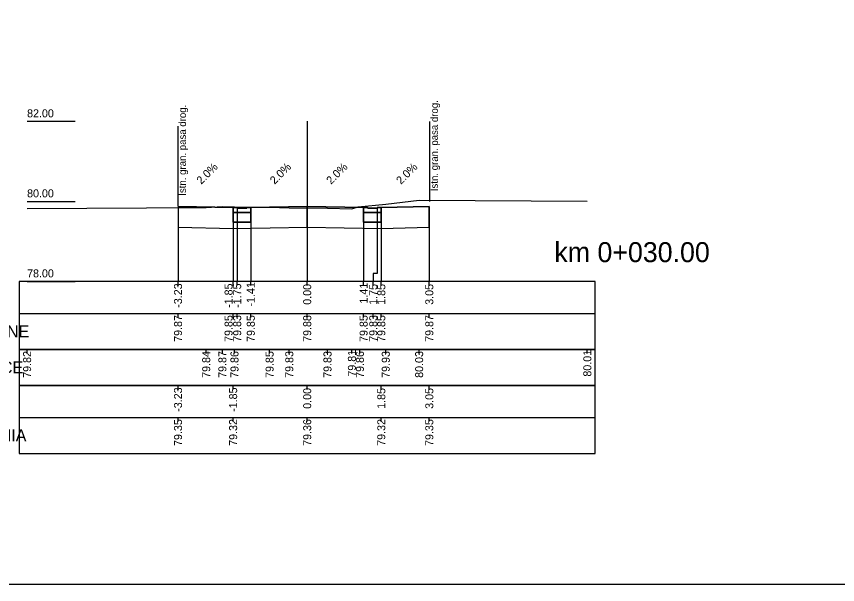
# Model space of a CAD drawing. Extents: x 7492871 to 7493499, y 5802964 to 5802992.
# Drawn here: x 7492882.66 to 7492903.18, y 5802963.88 to 5802978.08 of the extents above; entities that cross this region are included whole.
import ezdxf

# ---------------------------------------------------------------- set-up
doc = ezdxf.new("R2010")
doc.units = 0
for name, color, linetype in [('_wydruk', 7, 'Continuous'), ('opisy_ramki_pop', 7, 'Continuous'), ('pop_comp_kostka', 7, 'Continuous'), ('pop_comp_lawa', 7, 'Continuous'), ('pop_comp_scieralna', 7, 'Continuous'), ('pop_granica_istn', 7, 'Continuous'), ('pop_opis', 7, 'Continuous'), ('pop_os', 7, 'Continuous'), ('pop_pikietaz', 7, 'Continuous'), ('pop_teren', 7, 'Continuous')]:
    doc.layers.add(name, color=color, linetype=linetype)

msp = doc.modelspace()

# ---------------------------------------------------------------- linework, layer by layer
msp.add_lwpolyline([(7492886.697, 5802973.334), (7492888.074, 5802973.306), (7492888.174, 5802973.306), (7492888.175, 5802973.286), (7492888.414, 5802973.286), (7492888.415, 5802973.306), (7492888.515, 5802973.306), (7492889.925, 5802973.334), (7492891.335, 5802973.306), (7492891.435, 5802973.306), (7492891.436, 5802973.286), (7492891.675, 5802973.286), (7492891.676, 5802973.306), (7492891.776, 5802973.306), (7492892.976, 5802973.33)])
at = {"layer": '_wydruk'}
msp.add_lwpolyline([(7492871.369, 5802992.281), (7493499.283, 5802992.281), (7493499.283, 5802963.881), (7492871.369, 5802963.881)], close=True, dxfattribs=at)
at = {"layer": 'opisy_ramki_pop'}
for points in [[(7492886.697, 5802972.814), (7492886.697, 5802971.659), (7492886.697, 5802971.659), (7492886.697, 5802971.459)], [(7492888.074, 5802972.777), (7492888.074, 5802971.659), (7492888.074, 5802971.659), (7492888.074, 5802971.459)], [(7492889.925, 5802972.814), (7492889.925, 5802971.659), (7492889.925, 5802971.659), (7492889.925, 5802971.459)], [(7492891.776, 5802972.777), (7492891.776, 5802971.659), (7492891.776, 5802971.659), (7492891.776, 5802971.459)], [(7492892.976, 5802972.81), (7492892.976, 5802971.659), (7492892.976, 5802971.659), (7492892.976, 5802971.459)]]:
    msp.add_lwpolyline(points, dxfattribs=at)
at = {"layer": 'pop_comp_kostka'}
for p, q in [((7492888.174, 5802973.306), (7492888.074, 5802973.306)), ((7492888.074, 5802973.306), (7492888.074, 5802973.176)), ((7492888.074, 5802973.176), (7492888.515, 5802973.176)), ((7492888.175, 5802973.286), (7492888.174, 5802973.306)), ((7492888.414, 5802973.286), (7492888.175, 5802973.286)), ((7492888.415, 5802973.306), (7492888.414, 5802973.286)), ((7492888.515, 5802973.306), (7492888.415, 5802973.306)), ((7492888.515, 5802973.176), (7492888.515, 5802973.306)), ((7492891.435, 5802973.306), (7492891.335, 5802973.306)), ((7492891.335, 5802973.306), (7492891.335, 5802973.176)), ((7492891.335, 5802973.176), (7492891.776, 5802973.176)), ((7492891.436, 5802973.286), (7492891.435, 5802973.306)), ((7492891.675, 5802973.286), (7492891.436, 5802973.286)), ((7492891.676, 5802973.306), (7492891.675, 5802973.286)), ((7492891.776, 5802973.306), (7492891.676, 5802973.306)), ((7492891.776, 5802973.176), (7492891.776, 5802973.306))]:
    msp.add_line(p, q, dxfattribs=at)
at = {"layer": 'pop_comp_lawa'}
for p, q in [((7492888.515, 5802973.176), (7492888.074, 5802973.176)), ((7492888.074, 5802973.176), (7492888.074, 5802972.936)), ((7492888.515, 5802972.936), (7492888.515, 5802973.176)), ((7492891.776, 5802973.176), (7492891.335, 5802973.176)), ((7492891.335, 5802973.176), (7492891.335, 5802972.936)), ((7492891.776, 5802972.936), (7492891.776, 5802973.176)), ((7492888.074, 5802972.936), (7492888.515, 5802972.936)), ((7492891.335, 5802972.936), (7492891.776, 5802972.936))]:
    msp.add_line(p, q, dxfattribs=at)
at = {"layer": 'pop_comp_scieralna'}
for p, q in [((7492888.074, 5802973.306), (7492886.697, 5802973.334)), ((7492886.697, 5802973.334), (7492886.697, 5802972.814)), ((7492888.074, 5802972.936), (7492888.074, 5802973.306)), ((7492889.925, 5802973.334), (7492888.515, 5802973.306)), ((7492888.515, 5802973.306), (7492888.515, 5802972.936)), ((7492889.925, 5802972.814), (7492889.925, 5802973.334)), ((7492891.335, 5802973.306), (7492889.925, 5802973.334)), ((7492889.925, 5802973.334), (7492889.925, 5802972.814)), ((7492891.335, 5802972.936), (7492891.335, 5802973.306)), ((7492892.976, 5802973.33), (7492891.776, 5802973.306)), ((7492891.776, 5802973.306), (7492891.776, 5802972.936)), ((7492892.976, 5802972.81), (7492892.976, 5802973.33)), ((7492886.697, 5802972.814), (7492888.074, 5802972.777)), ((7492888.515, 5802972.936), (7492888.074, 5802972.936)), ((7492888.074, 5802972.777), (7492889.925, 5802972.814)), ((7492889.925, 5802972.814), (7492891.776, 5802972.777)), ((7492891.776, 5802972.936), (7492891.335, 5802972.936)), ((7492891.776, 5802972.777), (7492892.976, 5802972.81))]:
    msp.add_line(p, q, dxfattribs=at)
at = {"layer": 'pop_granica_istn'}
for p, q in [((7492892.993, 5802973.952), (7492892.993, 5802975.452)), ((7492886.697, 5802973.838), (7492886.697, 5802975.338)), ((7492886.697, 5802973.338), (7492886.697, 5802973.838)), ((7492892.993, 5802973.452), (7492892.993, 5802973.952))]:
    msp.add_line(p, q, dxfattribs=at)
at = {"layer": 'pop_opis'}
for p, q in [((7492882.925, 5802975.459), (7492884.125, 5802975.459)), ((7492882.925, 5802973.459), (7492884.125, 5802973.459)), ((7492882.725, 5802971.459), (7492882.725, 5802969.759)), ((7492882.725, 5802971.459), (7492882.725, 5802969.759)), ((7492882.725, 5802971.459), (7492882.725, 5802969.759)), ((7492882.725, 5802971.459), (7492882.725, 5802969.759)), ((7492882.925, 5802971.459), (7492884.125, 5802971.459)), ((7492886.697, 5802971.359), (7492886.697, 5802971.459)), ((7492888.074, 5802971.359), (7492888.074, 5802971.459)), ((7492888.175, 5802971.359), (7492888.175, 5802971.459)), ((7492888.515, 5802971.359), (7492888.515, 5802971.459)), ((7492889.925, 5802971.359), (7492889.925, 5802971.459)), ((7492891.335, 5802971.359), (7492891.335, 5802971.459)), ((7492891.576, 5802971.359), (7492891.576, 5802971.459)), ((7492891.776, 5802971.359), (7492891.776, 5802971.459)), ((7492892.976, 5802971.359), (7492892.976, 5802971.459)), ((7492882.725, 5802970.659), (7492897.125, 5802970.659)), ((7492882.725, 5802970.659), (7492897.125, 5802970.659)), ((7492882.725, 5802970.659), (7492897.125, 5802970.659)), ((7492882.725, 5802970.659), (7492897.125, 5802970.659)), ((7492886.697, 5802970.559), (7492886.697, 5802970.659)), ((7492888.074, 5802970.559), (7492888.074, 5802970.659)), ((7492888.175, 5802970.559), (7492888.175, 5802970.659)), ((7492888.515, 5802970.559), (7492888.515, 5802970.659)), ((7492889.925, 5802970.559), (7492889.925, 5802970.659)), ((7492891.335, 5802970.559), (7492891.335, 5802970.659)), ((7492891.576, 5802970.559), (7492891.576, 5802970.659)), ((7492891.776, 5802970.559), (7492891.776, 5802970.659)), ((7492892.976, 5802970.559), (7492892.976, 5802970.659)), ((7492882.725, 5802969.759), (7492882.725, 5802968.859)), ((7492882.925, 5802969.659), (7492882.925, 5802969.759)), ((7492887.401, 5802969.659), (7492887.401, 5802969.759)), ((7492887.805, 5802969.659), (7492887.805, 5802969.759)), ((7492888.108, 5802969.659), (7492888.108, 5802969.759)), ((7492888.985, 5802969.659), (7492888.985, 5802969.759)), ((7492889.477, 5802969.659), (7492889.477, 5802969.759)), ((7492890.432, 5802969.659), (7492890.432, 5802969.759)), ((7492891.042, 5802969.659), (7492891.042, 5802969.759)), ((7492891.242, 5802969.659), (7492891.242, 5802969.759)), ((7492891.888, 5802969.659), (7492891.888, 5802969.759)), ((7492892.722, 5802969.659), (7492892.722, 5802969.759)), ((7492896.925, 5802969.659), (7492896.925, 5802969.759)), ((7492882.725, 5802968.859), (7492882.725, 5802967.159)), ((7492886.697, 5802968.759), (7492886.697, 5802968.859)), ((7492888.074, 5802968.759), (7492888.074, 5802968.859)), ((7492889.925, 5802968.759), (7492889.925, 5802968.859)), ((7492891.776, 5802968.759), (7492891.776, 5802968.859)), ((7492892.976, 5802968.759), (7492892.976, 5802968.859)), ((7492882.725, 5802968.059), (7492897.125, 5802968.059)), ((7492886.697, 5802967.959), (7492886.697, 5802968.059)), ((7492888.074, 5802967.959), (7492888.074, 5802968.059)), ((7492889.925, 5802967.959), (7492889.925, 5802968.059)), ((7492891.776, 5802967.959), (7492891.776, 5802968.059)), ((7492892.976, 5802967.959), (7492892.976, 5802968.059))]:
    msp.add_line(p, q, dxfattribs=at)
for points in [[(7492886.697, 5802973.334), (7492886.697, 5802971.659), (7492886.697, 5802971.659), (7492886.697, 5802971.459)], [(7492888.074, 5802973.306), (7492888.074, 5802971.659), (7492888.074, 5802971.659), (7492888.074, 5802971.459)], [(7492888.175, 5802973.286), (7492888.175, 5802971.659), (7492888.175, 5802971.659), (7492888.175, 5802971.459)], [(7492888.515, 5802973.306), (7492888.515, 5802971.659), (7492888.515, 5802971.659), (7492888.515, 5802971.459)], [(7492889.925, 5802973.334), (7492889.925, 5802971.659), (7492889.925, 5802971.659), (7492889.925, 5802971.459)], [(7492891.335, 5802973.306), (7492891.335, 5802971.659), (7492891.335, 5802971.659), (7492891.335, 5802971.459)], [(7492891.675, 5802973.286), (7492891.675, 5802971.659), (7492891.576, 5802971.659), (7492891.576, 5802971.459)], [(7492891.776, 5802973.306), (7492891.776, 5802971.659), (7492891.776, 5802971.659), (7492891.776, 5802971.459)], [(7492892.976, 5802973.33), (7492892.976, 5802971.659), (7492892.976, 5802971.659), (7492892.976, 5802971.459)]]:
    msp.add_lwpolyline(points, dxfattribs=at)
for points in [[(7492882.725, 5802971.459), (7492882.725, 5802969.759), (7492897.125, 5802969.759), (7492897.125, 5802971.459)], [(7492882.725, 5802971.459), (7492882.725, 5802969.759), (7492897.125, 5802969.759), (7492897.125, 5802971.459)], [(7492882.725, 5802971.459), (7492882.725, 5802969.759), (7492897.125, 5802969.759), (7492897.125, 5802971.459)], [(7492882.725, 5802971.459), (7492882.725, 5802969.759), (7492897.125, 5802969.759), (7492897.125, 5802971.459)], [(7492882.725, 5802969.759), (7492882.725, 5802968.859), (7492897.125, 5802968.859), (7492897.125, 5802969.759)], [(7492882.725, 5802968.859), (7492882.725, 5802967.159), (7492897.125, 5802967.159), (7492897.125, 5802968.859)]]:
    msp.add_lwpolyline(points, close=True, dxfattribs=at)
at = {"layer": 'pop_os'}
msp.add_line((7492889.925, 5802975.459), (7492889.925, 5802971.459), dxfattribs=at)
at = {"layer": 'pop_teren'}
msp.add_lwpolyline([(7492882.925, 5802973.281), (7492887.401, 5802973.303), (7492887.805, 5802973.333), (7492888.108, 5802973.323), (7492888.985, 5802973.313), (7492889.477, 5802973.293), (7492890.432, 5802973.285), (7492891.042, 5802973.271), (7492891.195, 5802973.32), (7492891.888, 5802973.385), (7492892.722, 5802973.489), (7492896.925, 5802973.467)], dxfattribs=at)

# ---------------------------------------------------------------- texts
at = {"layer": 'pop_granica_istn'}
for p in [(7492886.895, 5802973.599), (7492893.191, 5802973.713)]:
    msp.add_text('Istn. gran. pasa drog.', height=0.18, rotation=90, dxfattribs=at).set_placement(p)
at = {"layer": 'pop_opis'}
for s, height, p in [('82.00', 0.2, (7492882.925, 5802975.559)), ('80.00', 0.2, (7492882.925, 5802973.559)), ('78.00', 0.2, (7492882.925, 5802971.559)), ('RZĘDNE PROJEKTOWANE', 0.3, (7492877.853, 5802970.059)), ('RZĘDNE PROJEKTOWANE', 0.3, (7492877.853, 5802970.059)), ('RZĘDNE PROJEKTOWANE', 0.3, (7492877.853, 5802970.059)), ('RZĘDNE PROJEKTOWANE', 0.3, (7492877.853, 5802970.059)), ('RZĘDNE ISTNIEJĄCE', 0.3, (7492878.749, 5802969.159)), ('RZĘDNE KORYTOWANIA', 0.3, (7492878.139, 5802967.459))]:
    msp.add_text(s, height=height, dxfattribs=at).set_placement(p)
for s, rotation, p in [('2.0%', 45, (7492887.277, 5802973.87)), ('2.0%', 45, (7492889.111, 5802973.87)), ('2.0%', 45, (7492890.521, 5802973.87)), ('2.0%', 45, (7492892.267, 5802973.868)), ('-3.23', 90, (7492886.797, 5802970.798)), ('-1.85', 90, (7492888.06, 5802970.796)), ('-1.75', 90, (7492888.275, 5802970.796)), ('-1.41', 90, (7492888.615, 5802970.829)), ('0.00', 90, (7492890.025, 5802970.874)), ('1.41', 90, (7492891.435, 5802970.905)), ('1.75', 90, (7492891.676, 5802970.873)), ('1.85', 90, (7492891.876, 5802970.873)), ('3.05', 90, (7492893.076, 5802970.873)), ('79.87', 90, (7492886.797, 5802969.947)), ('79.85', 90, (7492888.06, 5802969.945)), ('79.83', 90, (7492888.275, 5802969.947)), ('79.85', 90, (7492888.615, 5802969.945)), ('79.88', 90, (7492890.025, 5802969.946)), ('79.85', 90, (7492891.435, 5802969.945)), ('79.83', 90, (7492891.676, 5802969.947)), ('79.85', 90, (7492891.876, 5802969.945)), ('79.87', 90, (7492893.076, 5802969.947)), ('79.82', 90, (7492883.025, 5802969.048)), ('79.84', 90, (7492887.501, 5802969.047)), ('79.87', 90, (7492887.905, 5802969.047)), ('79.86', 90, (7492888.208, 5802969.047)), ('79.85', 90, (7492889.085, 5802969.045)), ('79.83', 90, (7492889.577, 5802969.047)), ('79.83', 90, (7492890.532, 5802969.047)), ('79.81', 90, (7492891.142, 5802969.078)), ('79.86', 90, (7492891.342, 5802969.047)), ('79.93', 90, (7492891.988, 5802969.047)), ('80.03', 90, (7492892.822, 5802969.047)), ('80.01', 90, (7492897.025, 5802969.078)), ('-3.23', 90, (7492886.797, 5802968.198)), ('-1.85', 90, (7492888.174, 5802968.196)), ('0.00', 90, (7492890.025, 5802968.274)), ('1.85', 90, (7492891.876, 5802968.273)), ('3.05', 90, (7492893.076, 5802968.273)), ('79.35', 90, (7492886.797, 5802967.345)), ('79.32', 90, (7492888.174, 5802967.348)), ('79.36', 90, (7492890.025, 5802967.347)), ('79.32', 90, (7492891.876, 5802967.348)), ('79.35', 90, (7492893.076, 5802967.345))]:
    msp.add_text(s, height=0.2, rotation=rotation, dxfattribs=at).set_placement(p)
at = {"layer": 'pop_pikietaz'}
msp.add_text('km 0+030.00', height=0.5, dxfattribs=at).set_placement((7492896.101, 5802971.939))

doc.saveas('drawing.dxf')
